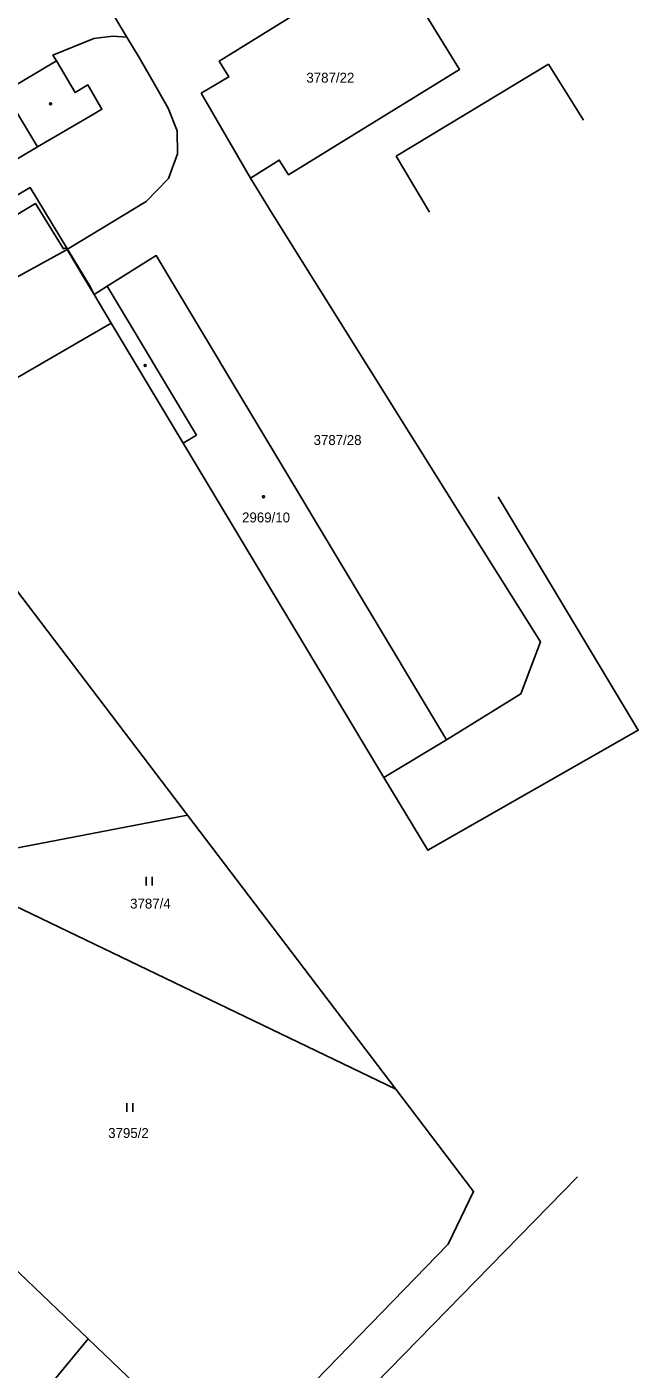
# Model space of a CAD drawing. Extents: x -527335 to -526256, y -1079142 to -1077809.
# Drawn here: x -526473.7 to -526369, y -1078894.6 to -1078664.8 of the extents above; entities that cross this region are included whole.
import ezdxf

# ---------------------------------------------------------------- set-up
doc = ezdxf.new("R2010")
doc.units = 0
for name, color, linetype in [('Vrstva 1', 7, 'Continuous'), ('Vrstva 2', 7, 'Continuous'), ('Vrstva 3', 7, 'Continuous'), ('Vrstva 4', 7, 'Continuous'), ('Vrstva 5', 7, 'Continuous')]:
    doc.layers.add(name, color=color, linetype=linetype)

msp = doc.modelspace()

# ---------------------------------------------------------------- linework, layer by layer
at = {"layer": 'Vrstva 1'}
for p, q in [((-526456.6, -1078666.52), (-526460.45, -1078660.06)), ((-526443.9, -1078676.11), (-526435.4, -1078690.65)), ((-526462.23, -1078710.59), (-526459.29, -1078715.49)), ((-526412.59, -1078793.3), (-526401.86, -1078786.86)), ((-526490.41, -1078808.25), (-526446.22, -1078799.76)), ((-526410.53, -1078846.68), (-526446.22, -1078799.76)), ((-526490.41, -1078808.25), (-526410.53, -1078846.68)), ((-526477.68, -1078875.63), (-526463.23, -1078889.43)), ((-526463.23, -1078889.43), (-526494.04, -1078926.52)), ((-526463.23, -1078889.43), (-526439.43, -1078912.18))]:
    msp.add_line(p, q, dxfattribs=at)
for points in [[(-526443.9, -1078676.11), (-526439.15, -1078673.33), (-526440.79, -1078670.66), (-526411.59, -1078652.55), (-526399.61, -1078672.09), (-526428.92, -1078690.08), (-526430.5, -1078687.59), (-526435.4, -1078690.65)], [(-526468.68, -1078670.61), (-526469.29, -1078669.59), (-526462.28, -1078666.74), (-526459.03, -1078666.34), (-526456.6, -1078666.52)], [(-526466.75, -1078702.85), (-526453.28, -1078694.69), (-526449.45, -1078690.73), (-526447.95, -1078686.51), (-526447.99, -1078682.56), (-526449.52, -1078678.69), (-526452.57, -1078673.36), (-526454.51, -1078670.02), (-526456.6, -1078666.52)], [(-526489.02, -1078681.76), (-526502.8, -1078689.9), (-526496.73, -1078700.04), (-526471.91, -1078685.32), (-526462.19, -1078679.64), (-526460.89, -1078678.88), (-526463.29, -1078674.7), (-526465.49, -1078675.98), (-526468.68, -1078670.61)], [(-526468.68, -1078670.61), (-526477.58, -1078675.89), (-526477.94, -1078675.21), (-526489.02, -1078681.76)], [(-526462.23, -1078710.59), (-526463.8, -1078707.96), (-526466.85, -1078702.91), (-526467.03, -1078702.61), (-526467.49, -1078702.78), (-526472.28, -1078695.01), (-526498.02, -1078710.48), (-526500.77, -1078711.52), (-526509.45, -1078708.26), (-526551.68, -1078690.31), (-526565.07, -1078683.93), (-526564.67, -1078683.01)], [(-526466.75, -1078702.85), (-526473.18, -1078692.3), (-526502.09, -1078709.21), (-526504.91, -1078709.68), (-526552.77, -1078689.34), (-526564.67, -1078683.01)], [(-526435.4, -1078690.65), (-526431.69, -1078696.75), (-526399.26, -1078748.53), (-526385.76, -1078770.08), (-526389.12, -1078778.99), (-526401.86, -1078786.86)], [(-526462.23, -1078710.59), (-526463.05, -1078708.92), (-526463.68, -1078707.89), (-526466.75, -1078702.85)], [(-526401.86, -1078786.86), (-526448.44, -1078709.15), (-526451.57, -1078703.93), (-526459.97, -1078709.18), (-526462.23, -1078710.59)], [(-526516.89, -1078712.01), (-526480.01, -1078727.48), (-526459.29, -1078715.49)], [(-526459.29, -1078715.49), (-526446.98, -1078736.06), (-526412.59, -1078793.3)], [(-526446.22, -1078799.76), (-526494.18, -1078736.71), (-526500.66, -1078729.66)], [(-526393.01, -1078745.25), (-526369.01, -1078785.21), (-526405.04, -1078805.76), (-526412.59, -1078793.3)], [(-526410.53, -1078846.68), (-526397.22, -1078864.18), (-526401.55, -1078873.2), (-526439.43, -1078912.18)], [(-526464.58, -1078955.73), (-526463.83, -1078947.95), (-526379.39, -1078861.67)]]:
    msp.add_lwpolyline(points, dxfattribs=at)
at = {"layer": 'Vrstva 3'}
for p, q in [((-526453.29, -1078811.8), (-526453.29, -1078810.3)), ((-526452.29, -1078811.8), (-526452.29, -1078810.3)), ((-526456.6, -1078850.57), (-526456.6, -1078849.07)), ((-526455.6, -1078850.57), (-526455.6, -1078849.07))]:
    msp.add_line(p, q, dxfattribs=at)
at = {"layer": 'Vrstva 4'}
for p, q in [((-526410.47, -1078686.93), (-526384.37, -1078671.18)), ((-526384.37, -1078671.18), (-526378.4, -1078680.72)), ((-526477.58, -1078675.89), (-526471.91, -1078685.32)), ((-526404.76, -1078696.48), (-526410.47, -1078686.93)), ((-526466.85, -1078702.91), (-526478.94, -1078709.54)), ((-526466.75, -1078702.85), (-526466.85, -1078702.91)), ((-526459.97, -1078709.18), (-526444.66, -1078734.67)), ((-526444.66, -1078734.67), (-526446.98, -1078736.06))]:
    msp.add_line(p, q, dxfattribs=at)
at = {"layer": 'Vrstva 5'}
for centre in [(-526469.67, -1078677.95), (-526453.48, -1078722.74), (-526433.19, -1078745.22)]:
    msp.add_circle(centre, 0.175, dxfattribs=at)

# ---------------------------------------------------------------- texts
at = {"layer": 'Vrstva 2'}
for s, p in [('3787/22', (-526425.85, -1078674.32)), ('3787/28', (-526424.62, -1078736.36)), ('2969/10', (-526436.87, -1078749.62)), ('3787/4', (-526456.05, -1078815.74)), ('3795/2', (-526459.81, -1078855.02))]:
    msp.add_text(s, height=1.7, dxfattribs=at).set_placement(p)

doc.saveas('drawing.dxf')
